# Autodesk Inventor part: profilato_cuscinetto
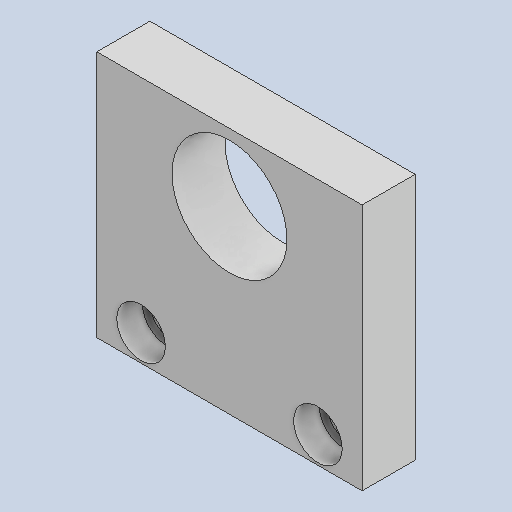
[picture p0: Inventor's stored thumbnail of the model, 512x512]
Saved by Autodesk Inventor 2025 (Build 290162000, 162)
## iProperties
Created: 2025-11
Part Number: profilato_cuscinetto
Material: Generico
Document SubType Name: Modeling
Designer: Ryzen5700u
Density: 1 g/cm^3
Appearance: Default
Author: Ryzen5700u
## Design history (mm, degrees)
feature "Solido2"
node "Solido1"
